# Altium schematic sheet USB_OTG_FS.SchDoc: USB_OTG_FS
size A4; DocumentNumber: 6; Revision: D.1(PCB.SCH); SheetNumber: 6; SheetTotal: 7
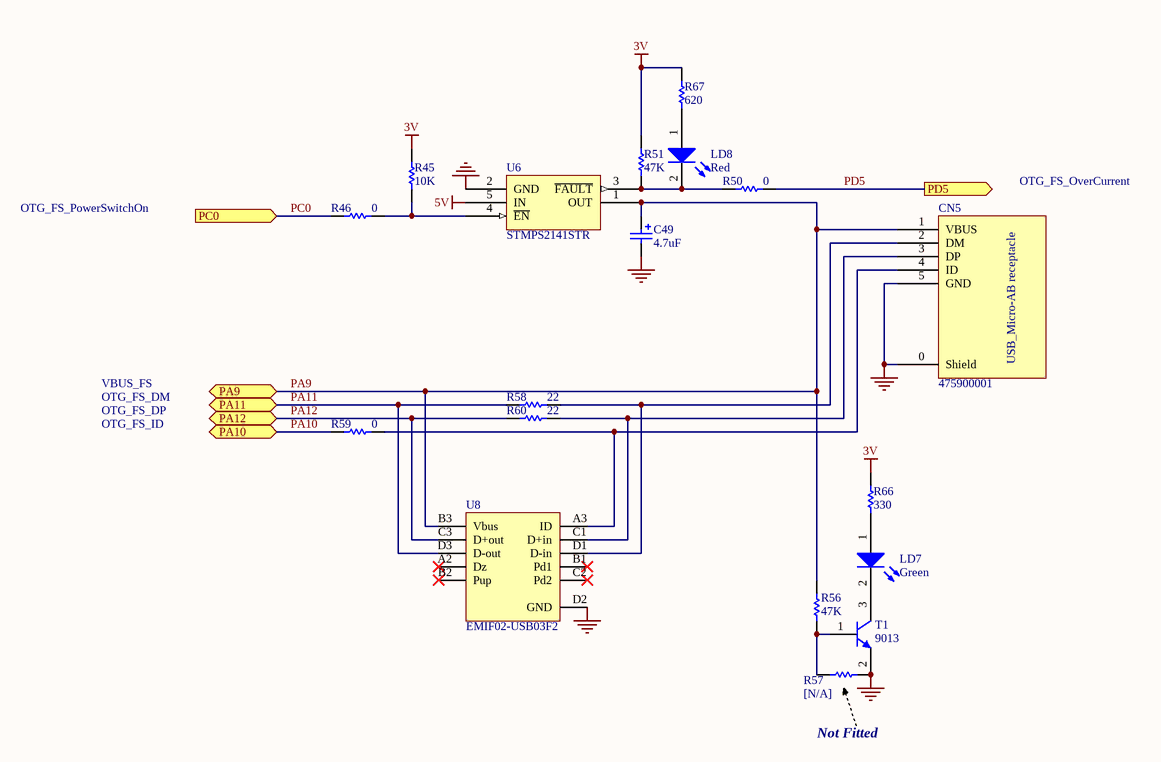
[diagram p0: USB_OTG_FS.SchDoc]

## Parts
C49  4.7uF  [CASE-A]
CN5  475900001  [USB-MICRO-AB_new]
LD7  Green  [LED0603]
LD8  Red  [LED0603]
R45  10K  [0402R]
R46  0  [0603R]
R50  0  [0603R]
R51  47K  [0402R]
R56  47K  [0402R]
R57  [N/A]  [0603R]
R58  22  [0402R]
R59  0  [0603R]
R60  22  [0402R]
R66  330  [0603R]
R67  620  [0603R]
T1  9013  [SOT23]
U6  STMPS2141STR  [SOT-23-5L]
U8  EMIF02-USB03F2  [FLIPCHIP(11)]

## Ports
PA9 (bidir), PA10 (bidir), PA11 (bidir), PA12 (bidir), PC0 (in), PD5 (out)

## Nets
3V: R45.1 R51.1 R66.2 R67.2
5V: U6.5(IN)
GND: C49.2 CN5.0(Shield) CN5.5(GND) R57.1 T1.2(E) U6.2(GND) U8.D2(GND)
PA9: C49.1 CN5.1(VBUS) R56.2 U6.1(OUT) U8.B3(Vbus) ; port PA9
PA10: R59.2 ; port PA10
PA11: R58.2 U8.D3(D-out) ; port PA11
PA12: R60.2 U8.C3(D+out) ; port PA12
PC0: R46.2 ; port PC0
PD5: R50.1 ; port PD5
NetCN5_2: CN5.2(DM) R58.1 U8.D1(D-in)
NetCN5_3: CN5.3(DP) R60.1 U8.C1(D+in)
NetCN5_4: CN5.4(ID) R59.1 U8.A3(ID)
NetLD7_1: LD7.1(A) R66.1
NetLD7_2: LD7.2(K) T1.3(C)
NetLD8_1: LD8.1(A) R67.1
NetLD8_2: LD8.2(K) R50.2 R51.2 U6.3(~{FAULT})
NetR45_2: R45.2 R46.1 U6.4(~{EN})
NetR56_1: R56.1 R57.2 T1.1(B)

Not connected (* = marked no-connect by the designer): U8 A2(Dz)* B1(Pd1)* B2(Pup)* C2(Pd2)*

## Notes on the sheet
- OTG_FS_PowerSwitchOn
- OTG_FS_OverCurrent
- VBUS_FS
- OTG_FS_ID
- OTG_FS_DM
- OTG_FS_DP
- Not Fitted

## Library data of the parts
C49 = Cap Pol1: Polarized Capacitor (Radial); Manuf_Part_1: TAJA475K016R; Manuf_1: AVX
CN5 = 475900001_: Manuf_Part_1: 47590-0001; Manuf_1: Molex; Value: 47590-0001
LD7 = LED2: Typical RED, GREEN, YELLOW, AMBER GaAs LED; Manuf_Part_1: 19-213SYGC/S530-E2/TR8; Manuf_1: EVERLIGHT
LD8 = LED2: Typical RED, GREEN, YELLOW, AMBER GaAs LED; Manuf_1: EVERLIGHT; Manuf_Part_1: 19-213-R6C-AP1Q2B-3T
R45 = res1: Resistor; Manuf_Part_1: RC0402FR-0710KL; Manuf_1: YAGEO
R46 R50 R59 = Res1: Resistor; Manuf_Part_1: RC0603JR-070RL; Manuf_1: YAGEO
R51 R56 = res1: Resistor; Manuf_Part_1: RC0402FR-0747KL; Manuf_1: YAGEO
R57 = res1: Resistor; Value: 1K; Fitted: NO
R58 R60 = Res1: Resistor; Manuf_Part_1: RC0402FR-0722RL; Manuf_1: YAGEO
R66 = res1: Resistor; Manuf_Part_1: RC0603FR-07330RL; Manuf_1: YAGEO
R67 = Res1: Resistor; Manuf_Part_1: RC0603FR-07620RL; Manuf_1: YAGEO
T1 = NPN_NEW: NPN Bipolar Transistor; Manuf_Part_1: MMBT9013; Manuf_1: unisonic; Code - JEDEC: TO-226-AA; Value: MMBT9013
U6 = STMPS2141STR: Enhanced single channel power switches; Manuf_1: STM; Provided: ST
U8 = EMIF02-USB03F2: 2-line IPAD, EMI filter including ESD protection; Manuf_1: STM; Provided: ST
